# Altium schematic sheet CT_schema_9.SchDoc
size 147 x 119 mm
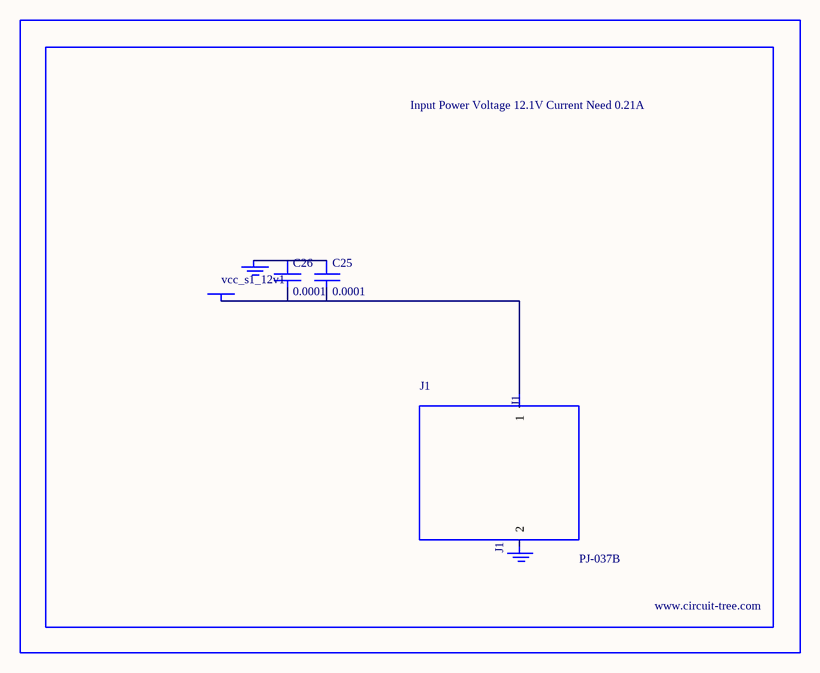
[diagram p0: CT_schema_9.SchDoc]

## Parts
BORDER8  (no value)
C25  0.0001  [EXV-9H]
C26  0.0001  [EXV-9H]
GND_INSTANCE_8_0  (no value)
GND_INSTANCE_8_1  (no value)
J1  PJ-037B  [PJ-037B_PACKAGE]
POWER_INSTANCE_8_0  vcc_s1_12v1

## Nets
NetC25_1: C25.1 C26.1 GND_INSTANCE_8_0.0(GND)
NetC25_2: C25.2 C26.2 J1.1 POWER_INSTANCE_8_0.0(PWR)

Not connected (* = marked no-connect by the designer): GND_INSTANCE_8_1 0(GND); J1 2

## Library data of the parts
BORDER8 = BORDER_PAGE8
C25 C26 = EDK107M035A9HAA
GND_INSTANCE_8_0 GND_INSTANCE_8_1 = GND
POWER_INSTANCE_8_0 = PWR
